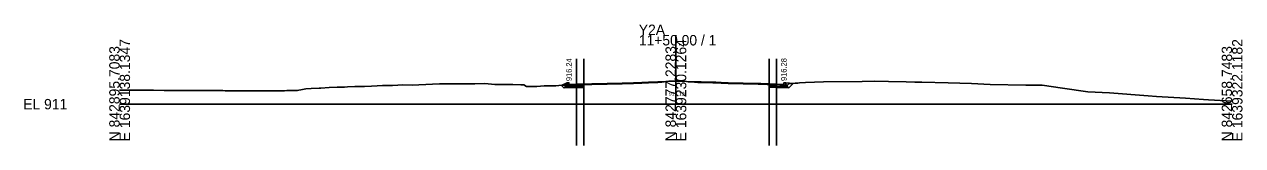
# Model space of a CAD drawing. Extents: x -26 to 303, y -10 to 10517.
# Drawn here: x -25.7 to 302.8, y 988.9 to 1021.4 of the extents above; entities that cross this region are included whole.
import ezdxf

# ---------------------------------------------------------------- set-up
doc = ezdxf.new("R2010")
doc.units = 0
for name, color, linetype in [('Exist Cross Section Cell', 7, 'Continuous'), ('Exist XS Center Line Elevation Label', 7, 'Continuous'), ('Exist XS Ground Line', 7, 'Continuous'), ('Prop CMT Conc Surface', 7, 'Continuous'), ('Prop CMT Concrete Structures', 7, 'Continuous'), ('Prop CMT Pvmt Course 1', 7, 'Continuous'), ('Prop CMT Pvmt Course 1 CG', 7, 'Continuous'), ('Prop CMT Pvmt Course 2', 7, 'Continuous'), ('Prop CMT Pvmt Surface Overlay', 7, 'Continuous'), ('Prop CMT Slope Grass', 7, 'Continuous'), ('Prop CMT Subgrade Earthwork', 7, 'Continuous'), ('Prop XS Hydro Elevations', 7, 'Continuous'), ('Scratch_Level_0', 7, 'Continuous'), ('Scratch_Level_2', 7, 'Continuous')]:
    doc.layers.add(name, color=color, linetype=linetype)

msp = doc.modelspace()

# ---------------------------------------------------------------- linework, layer by layer
at = {"layer": 'Exist Cross Section Cell'}
for p, q in [((150, 1000), (150, 1018.58)), ((0, 1000), (150, 1000)), ((150, 1000), (300, 1000))]:
    msp.add_line(p, q, dxfattribs=at)
at = {"layer": 'Exist XS Ground Line'}
msp.add_lwpolyline([(0, 1003.76), (1, 1003.75), (1.83, 1003.74), (2.48, 1003.74), (5.08, 1003.75), (5.64, 1003.75), (7.61, 1003.74), (8.81, 1003.73), (9.16, 1003.73), (11.97, 1003.71), (12.52, 1003.7), (13.23, 1003.7), (14.31, 1003.69), (15.14, 1003.68), (17.31, 1003.68), (18.3, 1003.68), (21.47, 1003.65), (23.21, 1003.65), (24.63, 1003.64), (25.12, 1003.64), (25.46, 1003.64), (27.8, 1003.63), (28.44, 1003.6), (29.54, 1003.61), (30.34, 1003.61), (30.97, 1003.6), (32.52, 1003.58), (33.61, 1003.6), (34.13, 1003.6), (35.24, 1003.59), (36.78, 1003.6), (37.5, 1003.59), (39.69, 1003.59), (40.38, 1003.59), (42.02, 1003.61), (43.46, 1003.62), (44.44, 1003.62), (45.06, 1003.63), (47.14, 1003.64), (47.89, 1003.65), (49.33, 1003.95), (50.24, 1004.15), (51.64, 1004.21), (53.78, 1004.31), (54.25, 1004.33), (56.51, 1004.43), (58.62, 1004.52), (60.62, 1004.6), (61.43, 1004.62), (63.45, 1004.7), (65.36, 1004.78), (66.03, 1004.78), (67.92, 1004.85), (69.45, 1004.91), (70.91, 1004.97), (71.9, 1004.98), (73.55, 1005.04), (75, 1005.1), (76.39, 1005.15), (78.9, 1005.12), (80.7, 1005.2), (86.25, 1005.44), (87.54, 1005.46), (93.33, 1005.43), (95.75, 1005.44), (98.44, 1005.51), (101.14, 1005.29), (102.33, 1005.25), (103.12, 1005.26), (103.59, 1005.25), (106.05, 1005.26), (108.15, 1005.23), (109.01, 1005.22), (109.73, 1004.74), (110.89, 1004.77), (112.5, 1004.78), (113.47, 1004.82), (114.52, 1004.88), (115.29, 1004.89), (115.66, 1004.9), (116.42, 1004.91), (117.65, 1004.94), (119.22, 1005.06), (119.59, 1005.09), (120.86, 1005.13), (122.99, 1005.21), (123.3, 1005.22), (124.77, 1005.26), (125.92, 1005.29), (127.37, 1005.32), (129.08, 1005.35), (130.12, 1005.37), (131.45, 1005.4), (132.25, 1005.42), (133.68, 1005.46), (135.53, 1005.48), (137.24, 1005.53), (138.58, 1005.58), (139.03, 1005.6), (139.6, 1005.63), (140.81, 1005.68), (141.74, 1005.71), (142.59, 1005.74), (143.68, 1005.79), (144.37, 1005.82), (145.11, 1005.84), (146.19, 1005.88), (146.8, 1006.04), (147.25, 1006.11), (148.07, 1006.18), (149.18, 1006.18), (150, 1006.19), (151.24, 1006.19), (151.56, 1006.18), (152.2, 1006.16), (152.88, 1006.1), (153.8, 1005.97), (155.06, 1005.88), (155.91, 1005.86), (156.84, 1005.84), (157.57, 1005.81), (158.62, 1005.79), (159.98, 1005.76), (160.73, 1005.75), (162.19, 1005.67), (164.06, 1005.58), (166.7, 1005.51), (167.26, 1005.51), (168.14, 1005.48), (170.23, 1005.42), (172.21, 1005.4), (172.88, 1005.39), (173.39, 1005.37), (174.66, 1005.32), (176.56, 1005.26), (178.07, 1005.2), (180.12, 1005.06), (180.56, 1005.52), (182.19, 1005.63), (182.93, 1005.68), (183.34, 1005.71), (184.99, 1005.8), (187.38, 1005.92), (189.79, 1005.96), (200.23, 1006.11), (203.64, 1006.19), (207.35, 1006.12), (212.13, 1006.02), (214.48, 1005.94), (216.3, 1005.89), (223.47, 1005.77), (229.76, 1005.51), (234.78, 1005.31), (244.35, 1005.13), (248.79, 1005.08), (254.29, 1004.3), (261.05, 1003.33), (266.95, 1003), (277.36, 1002.27), (279.61, 1002.08), (287.42, 1001.58), (292.27, 1001.29), (293.67, 1001.19), (300, 1000.8)], dxfattribs=at)
at = {"layer": 'Prop CMT Conc Surface'}
for points in [[(121.17, 1005.24), (121.17, 1005.74), (120.67, 1005.74)], [(179.12, 1005.27), (179.12, 1005.77), (179.62, 1005.77)]]:
    msp.add_lwpolyline(points, dxfattribs=at)
at = {"layer": 'Prop CMT Concrete Structures'}
for points in [[(123.17, 1005.36), (121.17, 1005.24), (121.17, 1005.74), (120.67, 1005.74)], [(120.67, 1005.74), (120.67, 1004.72), (123.17, 1004.77)], [(177.12, 1005.39), (179.12, 1005.27), (179.12, 1005.77), (179.62, 1005.77)], [(179.62, 1005.77), (179.62, 1004.76), (177.12, 1004.81)]]:
    msp.add_lwpolyline(points, dxfattribs=at)
at = {"layer": 'Prop CMT Pvmt Course 1'}
for p, q in [((123.17, 1005.36), (125.17, 1005.39)), ((123.17, 1005.36), (123.17, 1005.11)), ((125.17, 1005.39), (125.17, 1005.14)), ((175.12, 1005.43), (175.12, 1005.18)), ((177.12, 1005.39), (175.12, 1005.43)), ((177.12, 1005.39), (177.12, 1005.14)), ((123.17, 1005.11), (125.17, 1005.14)), ((177.12, 1005.14), (175.12, 1005.18))]:
    msp.add_line(p, q, dxfattribs=at)
at = {"layer": 'Prop CMT Pvmt Course 1 CG'}
for p, q in [((123.17, 1004.78), (123.17, 1004.44)), ((123.17, 1004.44), (125.17, 1004.48)), ((125.17, 1004.81), (125.17, 1004.48)), ((175.12, 1004.85), (175.12, 1004.52)), ((177.12, 1004.48), (175.12, 1004.52)), ((177.12, 1004.81), (177.12, 1004.48))]:
    msp.add_line(p, q, dxfattribs=at)
for points in [[(123.17, 1004.77), (120.17, 1004.71), (119.83, 1004.38)], [(119.87, 1004.38), (123.17, 1004.44)], [(177.12, 1004.81), (180.12, 1004.75), (180.46, 1004.41)], [(180.42, 1004.42), (177.12, 1004.48)]]:
    msp.add_lwpolyline(points, dxfattribs=at)
at = {"layer": 'Prop CMT Pvmt Course 2'}
for p, q in [((123.17, 1004.78), (123.17, 1005.11)), ((123.17, 1004.78), (125.17, 1004.81)), ((125.17, 1004.81), (125.17, 1005.14)), ((175.12, 1004.85), (175.12, 1005.18)), ((177.12, 1004.81), (175.12, 1004.85)), ((177.12, 1004.81), (177.12, 1005.14))]:
    msp.add_line(p, q, dxfattribs=at)
at = {"layer": 'Prop CMT Pvmt Surface Overlay'}
for points in [[(125.17, 1005.39), (125.92, 1005.41), (127.37, 1005.44), (129.08, 1005.47), (130.11, 1005.5), (131.45, 1005.52), (132.24, 1005.54), (133.68, 1005.59), (135.52, 1005.6), (137.24, 1005.65), (138.57, 1005.71), (139.02, 1005.73), (139.6, 1005.75), (140.8, 1005.8), (141.74, 1005.84), (142.58, 1005.87), (143.67, 1005.91), (144.37, 1005.94), (145.11, 1005.97), (146.75, 1006.02)], [(153.3, 1006.04), (155.91, 1005.98), (156.85, 1005.96), (157.57, 1005.94), (158.63, 1005.91), (159.99, 1005.89), (160.74, 1005.87), (162.19, 1005.79), (164.07, 1005.7), (166.7, 1005.64), (167.26, 1005.64), (168.14, 1005.6), (170.23, 1005.55), (172.22, 1005.53), (172.88, 1005.51), (173.4, 1005.49), (174.66, 1005.45), (175.12, 1005.43)]]:
    msp.add_lwpolyline(points, dxfattribs=at)
at = {"layer": 'Prop CMT Slope Grass'}
for points in [[(120.67, 1005.74), (119.16, 1005.05)], [(179.62, 1005.77), (181.63, 1005.59)]]:
    msp.add_lwpolyline(points, dxfattribs=at)
at = {"layer": 'Prop CMT Subgrade Earthwork'}
for points in [[(177.12, 1004.48), (180.46, 1004.41), (181.63, 1005.59)], [(123.17, 1004.44), (119.83, 1004.38), (119.16, 1005.05)]]:
    msp.add_lwpolyline(points, dxfattribs=at)
at = {"layer": 'Scratch_Level_0'}
for p, q in [((123.17, 1012.22), (123.17, 988.87)), ((125.17, 1012.22), (125.17, 988.87)), ((175.12, 1012.22), (175.12, 988.87)), ((177.12, 1012.22), (177.12, 988.87))]:
    msp.add_line(p, q, dxfattribs=at)
at = {"layer": 'Scratch_Level_2'}
for p, q in [((181.63, 1005.59), (180.56, 1005.52)), ((125.17, 1005.27), (124.77, 1005.26))]:
    msp.add_line(p, q, dxfattribs=at)
for points in [[(175.12, 1005.31), (175.12, 1004.52), (177.12, 1004.48), (180.46, 1004.41), (181.63, 1005.59)], [(175.12, 1005.31), (175.12, 1004.52), (177.12, 1004.48), (180.46, 1004.41), (181.63, 1005.59)], [(180.56, 1005.52), (180.12, 1005.06), (178.07, 1005.2), (176.56, 1005.26), (175.12, 1005.31)], [(119.16, 1005.05), (119.83, 1004.38), (123.17, 1004.44), (125.17, 1004.48), (125.17, 1005.27)], [(119.16, 1005.05), (119.83, 1004.38), (123.17, 1004.44), (125.17, 1004.48), (125.17, 1005.27)], [(124.77, 1005.26), (123.3, 1005.22), (122.99, 1005.21), (120.86, 1005.13), (119.59, 1005.09), (119.22, 1005.06), (119.16, 1005.05)]]:
    msp.add_lwpolyline(points, dxfattribs=at)

# ---------------------------------------------------------------- texts
at = {"layer": 'Exist Cross Section Cell'}
for s, p in [('Y2A', (140, 1018.58)), ('11+50.00 / 1', (140, 1015.78)), ('EL 911', (-26, 998.6))]:
    msp.add_text(s, height=2.8, dxfattribs=at).set_placement(p)
for s, p in [('N 842895.7083', (0, 990)), ('E 1639138.1347', (2.8, 990)), ('N 842777.2283', (150, 990)), ('E 1639230.1264', (152.8, 990)), ('N 842658.7483', (300, 990)), ('E 1639322.1182', (302.8, 990))]:
    msp.add_text(s, height=2.8, rotation=90, dxfattribs=at).set_placement(p)
at = {"layer": 'Exist XS Center Line Elevation Label'}
msp.add_text('917.19', height=1, dxfattribs=at).set_placement((148.12, 1002.3))
at = {"layer": 'Prop XS Hydro Elevations'}
for s, p in [('916.24', (121.92, 1006.19)), ('916.28', (179.87, 1006.23))]:
    msp.add_text(s, height=1.5, rotation=90, dxfattribs=at).set_placement(p)

doc.saveas('drawing.dxf')
